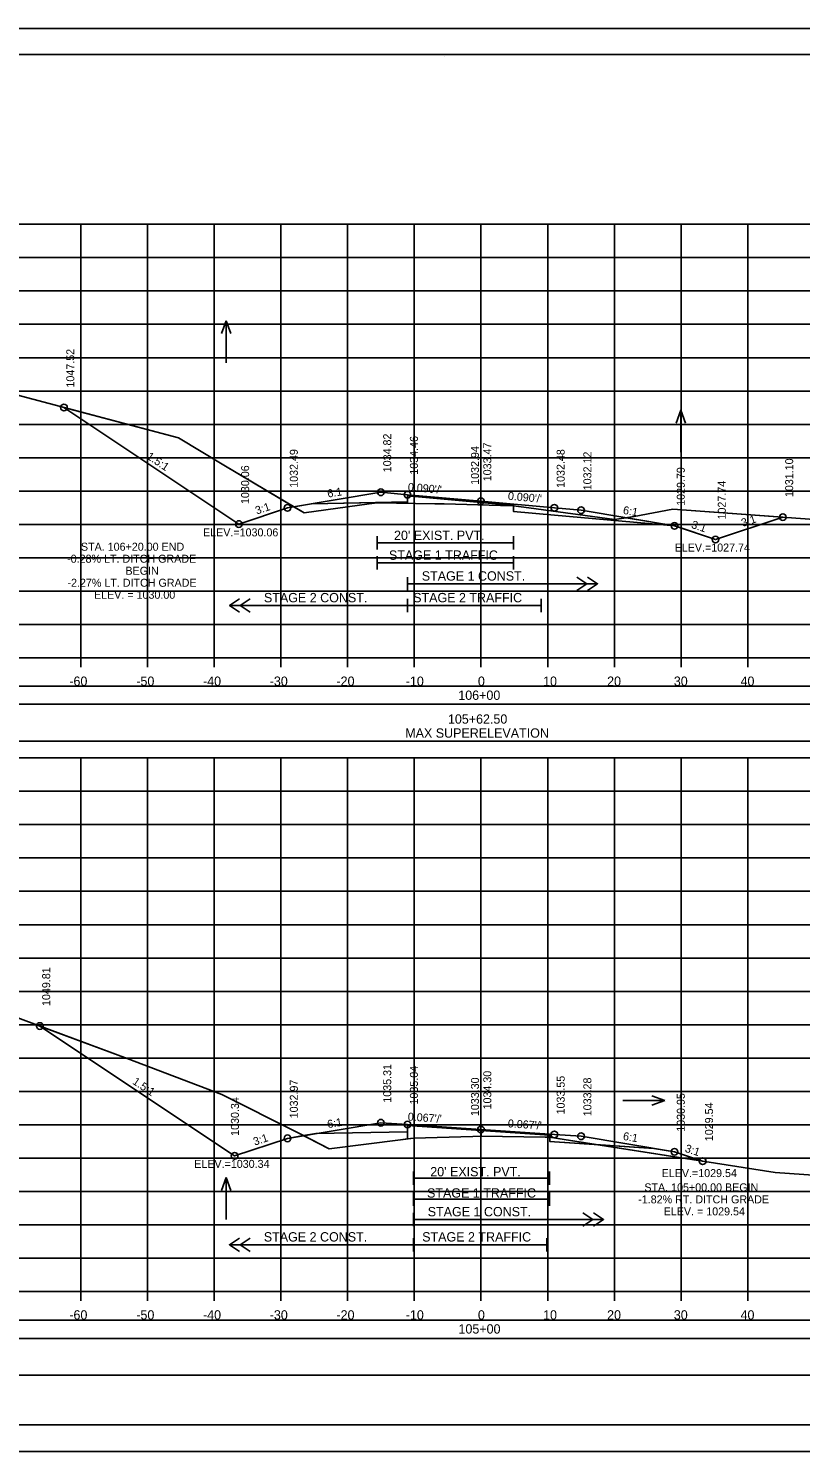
# Model space of a CAD drawing. Extents: x 1370565 to 1374448, y 301010 to 304637.
# Drawn here: x 1370667.2 to 1370782.9, y 301650.5 to 301863.8 of the extents above; entities that cross this region are included whole.
import ezdxf

# ---------------------------------------------------------------- set-up
doc = ezdxf.new("R2010")
doc.units = 0
for name, color, linetype in [('R_Alt Surface', 7, 'Continuous'), ('R_Axis', 7, 'Continuous'), ('R_Axis Annot', 7, 'Continuous'), ('R_Border', 7, 'Continuous'), ('R_Contours', 7, 'Continuous'), ('R_Drive', 7, 'Continuous'), ('R_Exist Surface', 7, 'Continuous'), ('R_Fin Surface', 7, 'Continuous'), ('R_Grid', 7, 'Continuous'), ('R_No Plot', 7, 'Continuous'), ('R_Water', 7, 'Continuous'), ('R_Water Annot', 7, 'Continuous'), ('R_Xsect Elev', 7, 'Continuous'), ('R_Xsect Slope', 7, 'Continuous')]:
    doc.layers.add(name, color=color, linetype=linetype)

msp = doc.modelspace()

# ---------------------------------------------------------------- linework, layer by layer
at = {"layer": 'R_Alt Surface'}
for points in [[(1370709.64, 301792.58), (1370724.03, 301792.87), (1370724.02, 301792.86), (1370724.03, 301793.78), (1370735.03, 301792.79), (1370739.91, 301792.35), (1370739.92, 301791.43), (1370746.03, 301790.89), (1370764.07, 301789.26)], [(1370719.47, 301787.72), (1370719.47, 301785.72)], [(1370739.91, 301787.72), (1370739.91, 301785.72)], [(1370719.47, 301786.72), (1370739.91, 301786.72)], [(1370719.47, 301784.74), (1370719.47, 301782.74)], [(1370719.47, 301783.74), (1370739.91, 301783.74)], [(1370739.91, 301784.74), (1370739.91, 301782.74)], [(1370724.03, 301781.6), (1370724.03, 301779.6)], [(1370749.42, 301781.6), (1370750.92, 301780.6), (1370749.42, 301779.6)], [(1370751.02, 301781.6), (1370752.52, 301780.6), (1370751.02, 301779.6)], [(1370724.03, 301780.6), (1370752.52, 301780.6)], [(1370698.84, 301778.34), (1370697.34, 301777.34), (1370698.84, 301776.34)], [(1370697.34, 301777.34), (1370724.03, 301777.34)], [(1370700.44, 301778.34), (1370698.94, 301777.34), (1370700.44, 301776.34)], [(1370724.03, 301778.34), (1370724.03, 301776.34)], [(1370724.03, 301777.34), (1370744.03, 301777.34)], [(1370744.04, 301778.34), (1370744.04, 301776.34)], [(1370710.26, 301698.17), (1370724.03, 301698.44), (1370724.02, 301698.44), (1370724.03, 301699.36), (1370735.03, 301698.62), (1370745.32, 301697.92), (1370745.33, 301697), (1370746.03, 301696.96), (1370760.95, 301695.95)], [(1370724.92, 301692.5), (1370724.92, 301690.5)], [(1370724.92, 301691.5), (1370745.32, 301691.5)], [(1370745.32, 301692.5), (1370745.32, 301690.5)], [(1370724.92, 301689.35), (1370724.92, 301687.35)], [(1370745.32, 301689.35), (1370745.32, 301687.35)], [(1370724.92, 301688.35), (1370745.32, 301688.35)], [(1370724.92, 301686.31), (1370724.92, 301684.31)], [(1370724.92, 301685.31), (1370753.41, 301685.31)], [(1370750.31, 301686.31), (1370751.81, 301685.31), (1370750.31, 301684.31)], [(1370751.91, 301686.31), (1370753.41, 301685.31), (1370751.91, 301684.31)], [(1370698.83, 301682.51), (1370697.33, 301681.51), (1370698.83, 301680.51)], [(1370697.33, 301681.51), (1370725.03, 301681.51)], [(1370700.43, 301682.51), (1370698.93, 301681.51), (1370700.43, 301680.51)], [(1370724.92, 301682.51), (1370724.92, 301680.51)], [(1370724.92, 301681.51), (1370744.92, 301681.51)], [(1370744.92, 301682.51), (1370744.92, 301680.51)]]:
    msp.add_lwpolyline(points, dxfattribs=at)
at = {"layer": 'R_Axis'}
for p, q in [((1370585.03, 301769.49), (1370885.03, 301769.49)), ((1370675.03, 301768.09), (1370675.03, 301769.49)), ((1370685.03, 301768.09), (1370685.03, 301769.49)), ((1370695.03, 301768.09), (1370695.03, 301769.49)), ((1370705.03, 301768.09), (1370705.03, 301769.49)), ((1370715.03, 301768.09), (1370715.03, 301769.49)), ((1370725.03, 301768.09), (1370725.03, 301769.49)), ((1370735.03, 301768.09), (1370735.03, 301769.49)), ((1370745.03, 301768.09), (1370745.03, 301769.49)), ((1370755.03, 301768.09), (1370755.03, 301769.49)), ((1370765.03, 301768.09), (1370765.03, 301769.49)), ((1370775.03, 301768.09), (1370775.03, 301769.49)), ((1370585.03, 301674.49), (1370885.03, 301674.49)), ((1370675.03, 301673.09), (1370675.03, 301674.49)), ((1370685.03, 301673.09), (1370685.03, 301674.49)), ((1370695.03, 301673.09), (1370695.03, 301674.49)), ((1370705.03, 301673.09), (1370705.03, 301674.49)), ((1370715.03, 301673.09), (1370715.03, 301674.49)), ((1370725.03, 301673.09), (1370725.03, 301674.49)), ((1370735.03, 301673.09), (1370735.03, 301674.49)), ((1370745.03, 301673.09), (1370745.03, 301674.49)), ((1370755.03, 301673.09), (1370755.03, 301674.49)), ((1370765.03, 301673.09), (1370765.03, 301674.49)), ((1370775.03, 301673.09), (1370775.03, 301674.49))]:
    msp.add_line(p, q, dxfattribs=at)
for points in [[(1370719.47, 301787.72), (1370719.47, 301785.72)], [(1370739.91, 301787.72), (1370739.91, 301785.72)], [(1370719.47, 301786.72), (1370739.91, 301786.72)], [(1370719.47, 301784.74), (1370719.47, 301782.74)], [(1370719.47, 301783.74), (1370739.91, 301783.74)], [(1370739.91, 301784.74), (1370739.91, 301782.74)], [(1370724.92, 301692.5), (1370724.92, 301690.5)], [(1370724.92, 301691.5), (1370745.32, 301691.5)], [(1370745.32, 301692.5), (1370745.32, 301690.5)], [(1370724.92, 301689.35), (1370724.92, 301687.35)], [(1370745.32, 301689.35), (1370745.32, 301687.35)], [(1370724.92, 301688.35), (1370745.32, 301688.35)]]:
    msp.add_lwpolyline(points, dxfattribs=at)
at = {"layer": 'R_Border'}
for p, q in [((1370577.03, 301859.95), (1370893.21, 301859.95)), ((1370729.55, 301859.69), (1370729.55, 301859.69)), ((1370729.55, 301859.69), (1370729.55, 301859.69)), ((1370893.21, 301654.49), (1370577.03, 301654.49))]:
    msp.add_line(p, q, dxfattribs=at)
at = {"layer": 'R_Contours'}
for p, q in [((1370706.99, 301792.14), (1370696.51, 301798.36)), ((1370709.64, 301792.58), (1370706.99, 301792.14)), ((1370719.47, 301792.78), (1370709.64, 301792.58)), ((1370724.03, 301792.87), (1370719.47, 301792.78)), ((1370724.02, 301792.66), (1370724.03, 301792.87)), ((1370724.02, 301792.86), (1370724.02, 301792.62)), ((1370756.79, 301790.48), (1370755.05, 301790.22)), ((1370756.79, 301790.48), (1370764.07, 301789.26)), ((1370764.07, 301789.26), (1370756.79, 301790.48)), ((1370708.45, 301697.87), (1370707.43, 301698.39)), ((1370710.26, 301698.17), (1370708.45, 301697.87)), ((1370724.03, 301698.44), (1370710.26, 301698.17)), ((1370724.02, 301698.44), (1370724.02, 301697.38)), ((1370724.02, 301697.38), (1370724.03, 301698.44)), ((1370724.03, 301698.44), (1370724.02, 301697.38)), ((1370735.06, 301698.62), (1370735.03, 301698.62)), ((1370735.06, 301698.62), (1370735.07, 301697.79)), ((1370735.07, 301697.79), (1370735.06, 301698.62)), ((1370745.33, 301697.64), (1370745.33, 301697)), ((1370760.95, 301695.95), (1370752.25, 301696.54)), ((1370752.25, 301696.54), (1370768.26, 301694.03))]:
    msp.add_line(p, q, dxfattribs=at)
for points in [[(1370696.51, 301798.36), (1370689.67, 301802.48), (1370672.53, 301807.01)], [(1370672.53, 301807.01), (1370698.73, 301789.55), (1370706.03, 301791.98), (1370706.99, 301792.14)], [(1370706.99, 301792.14), (1370708.53, 301791.22), (1370718.26, 301792.56), (1370719.47, 301792.72)], [(1370719.47, 301792.72), (1370719.47, 301792.78)], [(1370719.47, 301792.78), (1370719.47, 301792.72)], [(1370719.47, 301792.72), (1370724.02, 301792.66), (1370724.02, 301792.66)], [(1370755.05, 301790.22), (1370742.2, 301791.97), (1370739.91, 301792.3)], [(1370739.91, 301792.3), (1370739.92, 301791.43), (1370746.03, 301790.89), (1370764.07, 301789.26)], [(1370780.28, 301790.59), (1370763.8, 301791.8), (1370757.99, 301790.66), (1370756.79, 301790.48)], [(1370764.07, 301789.26), (1370770.18, 301787.23), (1370780.28, 301790.59)], [(1370707.43, 301698.39), (1370696.18, 301704.03), (1370681.98, 301709.45), (1370668.91, 301714.3)], [(1370668.91, 301714.3), (1370698.11, 301694.83), (1370706.03, 301697.46), (1370708.45, 301697.87)], [(1370708.45, 301697.87), (1370712.28, 301695.91), (1370722.96, 301697.24), (1370724.02, 301697.38)], [(1370724.02, 301697.38), (1370724.92, 301697.5), (1370733.82, 301697.75), (1370735.07, 301697.79)], [(1370735.03, 301698.62), (1370724.03, 301699.36), (1370724.03, 301698.44)], [(1370745.33, 301697.64), (1370745.32, 301697.92), (1370735.06, 301698.62)], [(1370735.07, 301697.79), (1370744.65, 301697.65), (1370745.32, 301697.64)], [(1370745.32, 301697.64), (1370745.33, 301697.64)], [(1370752.25, 301696.54), (1370747.49, 301697.29), (1370745.33, 301697.64)], [(1370745.33, 301697), (1370746.03, 301696.96), (1370752.25, 301696.54)], [(1370768.26, 301694.03), (1370764.03, 301695.44), (1370760.95, 301695.95)]]:
    msp.add_lwpolyline(points, dxfattribs=at)
at = {"layer": 'R_Drive'}
for points in [[(1370585.82, 301762.53), (1370884.24, 301762.53), (1370884.24, 301765.23), (1370585.82, 301765.23)], [(1370585.82, 301757.01), (1370884.24, 301757.01), (1370884.24, 301762.53), (1370585.82, 301762.53)], [(1370585.82, 301667.47), (1370884.24, 301667.47), (1370884.24, 301670.18), (1370585.82, 301670.18)], [(1370585.82, 301661.95), (1370884.24, 301661.95), (1370884.24, 301667.47), (1370585.82, 301667.47)]]:
    msp.add_lwpolyline(points, close=True, dxfattribs=at)
at = {"layer": 'R_Exist Surface'}
for points in [[(1370585.03, 301823.09), (1370587.14, 301822.88), (1370589.87, 301822.66), (1370596.68, 301822.02), (1370600.3, 301821.49), (1370655.44, 301811.49), (1370657.27, 301811.07), (1370659.72, 301810.4), (1370689.67, 301802.48), (1370696.51, 301798.36), (1370708.53, 301791.22), (1370718.26, 301792.56), (1370719.47, 301792.72), (1370728.13, 301792.6), (1370729.5, 301792.6), (1370737.94, 301792.35), (1370739.91, 301792.3), (1370742.2, 301791.97), (1370755.05, 301790.22), (1370757.99, 301790.66), (1370763.8, 301791.8), (1370791.83, 301789.74)], [(1370585.03, 301739.76), (1370654.67, 301719.57), (1370681.98, 301709.45), (1370696.18, 301704.03), (1370707.43, 301698.39), (1370712.28, 301695.91), (1370722.96, 301697.24), (1370724.92, 301697.5), (1370733.82, 301697.75), (1370735.07, 301697.79), (1370744.65, 301697.65), (1370745.32, 301697.64), (1370747.49, 301697.29), (1370779.11, 301692.32), (1370787.74, 301691.72), (1370818.07, 301689.7), (1370860.42, 301688.45), (1370868.77, 301688.21), (1370876.05, 301688.04), (1370885.03, 301687.88)]]:
    msp.add_lwpolyline(points, dxfattribs=at)
at = {"layer": 'R_Fin Surface'}
for points in [[(1370672.53, 301807.01), (1370698.73, 301789.55), (1370706.03, 301791.98), (1370720.03, 301794.31), (1370724.03, 301793.95), (1370735.03, 301792.96), (1370746.03, 301791.97), (1370750.03, 301791.61), (1370764.03, 301789.28), (1370770.18, 301787.23), (1370780.28, 301790.59)], [(1370668.91, 301714.3), (1370698.11, 301694.83), (1370706.03, 301697.46), (1370720.03, 301699.8), (1370724.03, 301699.53), (1370735.03, 301698.79), (1370746.03, 301698.04), (1370750.03, 301697.77), (1370764.03, 301695.44), (1370768.26, 301694.03)]]:
    msp.add_lwpolyline(points, dxfattribs=at)
at = {"layer": 'R_Grid'}
for p, q in [((1370585.03, 301834.49), (1370885.03, 301834.49)), ((1370675.03, 301769.49), (1370675.03, 301834.49)), ((1370685.03, 301769.49), (1370685.03, 301834.49)), ((1370695.03, 301769.49), (1370695.03, 301834.49)), ((1370705.03, 301769.49), (1370705.03, 301834.49)), ((1370715.03, 301769.49), (1370715.03, 301834.49)), ((1370725.03, 301769.49), (1370725.03, 301834.49)), ((1370735.03, 301769.49), (1370735.03, 301834.49)), ((1370745.03, 301769.49), (1370745.03, 301834.49)), ((1370755.03, 301769.49), (1370755.03, 301834.49)), ((1370765.03, 301769.49), (1370765.03, 301834.49)), ((1370775.03, 301769.49), (1370775.03, 301834.49)), ((1370585.03, 301829.49), (1370885.03, 301829.49)), ((1370585.03, 301824.49), (1370885.03, 301824.49)), ((1370585.03, 301819.49), (1370885.03, 301819.49)), ((1370585.03, 301814.49), (1370885.03, 301814.49)), ((1370585.03, 301809.49), (1370885.03, 301809.49)), ((1370585.03, 301804.49), (1370885.03, 301804.49)), ((1370585.03, 301799.49), (1370885.03, 301799.49)), ((1370585.03, 301794.49), (1370885.03, 301794.49)), ((1370585.03, 301789.49), (1370885.03, 301789.49)), ((1370585.03, 301784.49), (1370885.03, 301784.49)), ((1370585.03, 301779.49), (1370885.03, 301779.49)), ((1370585.03, 301774.49), (1370885.03, 301774.49)), ((1370585.03, 301769.49), (1370885.03, 301769.49)), ((1370585.03, 301754.49), (1370885.03, 301754.49)), ((1370675.03, 301674.49), (1370675.03, 301754.49)), ((1370685.03, 301674.49), (1370685.03, 301754.49)), ((1370695.03, 301674.49), (1370695.03, 301754.49)), ((1370705.03, 301674.49), (1370705.03, 301754.49)), ((1370715.03, 301674.49), (1370715.03, 301754.49)), ((1370725.03, 301674.49), (1370725.03, 301754.49)), ((1370735.03, 301674.49), (1370735.03, 301754.49)), ((1370745.03, 301674.49), (1370745.03, 301754.49)), ((1370755.03, 301674.49), (1370755.03, 301754.49)), ((1370765.03, 301674.49), (1370765.03, 301754.49)), ((1370775.03, 301674.49), (1370775.03, 301754.49)), ((1370585.03, 301749.49), (1370885.03, 301749.49)), ((1370585.03, 301744.49), (1370885.03, 301744.49)), ((1370585.03, 301739.49), (1370885.03, 301739.49)), ((1370585.03, 301734.49), (1370885.03, 301734.49)), ((1370585.03, 301729.49), (1370885.03, 301729.49)), ((1370585.03, 301724.49), (1370885.03, 301724.49)), ((1370585.03, 301719.49), (1370885.03, 301719.49)), ((1370585.03, 301714.49), (1370885.03, 301714.49)), ((1370585.03, 301709.49), (1370885.03, 301709.49)), ((1370585.03, 301704.49), (1370885.03, 301704.49)), ((1370585.03, 301699.49), (1370885.03, 301699.49)), ((1370585.03, 301694.49), (1370885.03, 301694.49)), ((1370585.03, 301689.49), (1370885.03, 301689.49)), ((1370585.03, 301684.49), (1370885.03, 301684.49)), ((1370585.03, 301679.49), (1370885.03, 301679.49)), ((1370585.03, 301674.49), (1370885.03, 301674.49))]:
    msp.add_line(p, q, dxfattribs=at)
at = {"layer": 'R_No Plot'}
for p, q in [((1370564.63, 301863.84), (1370897.96, 301863.84)), ((1370564.63, 301650.51), (1370897.96, 301650.51))]:
    msp.add_line(p, q, dxfattribs=at)
for points in [[(1370564.62, 301863.84), (1370897.96, 301863.84), (1370897.96, 301650.51), (1370564.62, 301650.51)], [(1370810.95, 301859.95), (1370830.57, 301859.95), (1370830.57, 301850.07), (1370846.68, 301850.07), (1370869.88, 301850.07), (1370869.88, 301817.4), (1370893.09, 301817.4), (1370893.21, 301654.49), (1370577.03, 301654.49), (1370577.03, 301859.95)]]:
    msp.add_lwpolyline(points, close=True, dxfattribs=at)
for centre in [(1370672.53, 301807.01), (1370720.03, 301794.31), (1370724.03, 301793.95), (1370706.03, 301791.98), (1370735.03, 301792.96), (1370746.03, 301791.97), (1370750.03, 301791.61), (1370698.73, 301789.55), (1370764.03, 301789.28), (1370780.28, 301790.59), (1370770.18, 301787.23), (1370668.91, 301714.3), (1370720.03, 301699.8), (1370724.03, 301699.53), (1370706.03, 301697.46), (1370735.03, 301698.79), (1370746.03, 301698.04), (1370750.03, 301697.77), (1370764.03, 301695.44), (1370698.11, 301694.83), (1370768.26, 301694.03)]:
    msp.add_circle(centre, 0.5, dxfattribs=at)
at = {"layer": 'R_Water Annot'}
for p, q in [((1370696.85, 301820.02), (1370696.15, 301818.1)), ((1370696.85, 301813.74), (1370696.85, 301820.02)), ((1370696.85, 301820.02), (1370697.55, 301818.1)), ((1370765.01, 301806.6), (1370764.31, 301804.67)), ((1370765.01, 301800.31), (1370765.01, 301806.6)), ((1370765.01, 301806.6), (1370765.71, 301804.67)), ((1370756.29, 301703.11), (1370762.57, 301703.11)), ((1370762.57, 301703.11), (1370760.65, 301703.81)), ((1370762.57, 301703.11), (1370760.65, 301702.41)), ((1370696.85, 301691.59), (1370696.15, 301689.66)), ((1370696.85, 301685.3), (1370696.85, 301691.59)), ((1370696.85, 301691.59), (1370697.55, 301689.66))]:
    msp.add_line(p, q, dxfattribs=at)
at = {"layer": 'R_Xsect Elev'}
for p, q in [((1370735.03, 301792.43), (1370735.03, 301802.43)), ((1370735.03, 301697.79), (1370735.03, 301707.79))]:
    msp.add_line(p, q, dxfattribs=at)

# ---------------------------------------------------------------- texts
at = {"layer": 'R_Axis Annot'}
for s, p in [("20' EXIST. PVT.", (1370722, 301787.16)), ('-60', (1370673.33, 301765.29)), ('-50', (1370683.37, 301765.29)), ('-40', (1370693.37, 301765.29)), ('-30', (1370703.37, 301765.29)), ('-20', (1370713.37, 301765.29)), ('-10', (1370723.76, 301765.29)), ('0', (1370734.57, 301765.29)), ('10', (1370744.34, 301765.29)), ('20', (1370753.94, 301765.29)), ('30', (1370763.94, 301765.29)), ('40', (1370773.94, 301765.29)), ('106+00', (1370731.63, 301763.19)), ('105+62.50', (1370730.08, 301759.62)), ('MAX SUPERELEVATION', (1370723.68, 301757.52)), ("20' EXIST. PVT.", (1370727.43, 301691.76)), ('-60', (1370673.33, 301670.29)), ('-50', (1370683.37, 301670.29)), ('-40', (1370693.37, 301670.29)), ('-30', (1370703.37, 301670.29)), ('-20', (1370713.37, 301670.29)), ('-10', (1370723.76, 301670.29)), ('0', (1370734.57, 301670.29)), ('10', (1370744.34, 301670.29)), ('20', (1370753.94, 301670.29)), ('30', (1370763.94, 301670.29)), ('40', (1370773.94, 301670.29)), ('105+00', (1370731.66, 301668.19))]:
    msp.add_text(s, height=1.4, dxfattribs=at).set_placement(p)
at = {"layer": 'R_Water'}
for s, p in [('STAGE 1 TRAFFIC', (1370721.24, 301784.19)), ('STAGE 1 CONST.', (1370726.16, 301781.07)), ('STAGE 2 CONST.', (1370702.5, 301777.82)), ('STAGE 2 TRAFFIC', (1370724.87, 301777.82)), ('STAGE 1 TRAFFIC', (1370726.95, 301688.57)), ('STAGE 1 CONST.', (1370727.05, 301685.77)), ('STAGE 2 CONST.', (1370702.48, 301681.99)), ('STAGE 2 TRAFFIC', (1370726.22, 301681.99))]:
    msp.add_text(s, height=1.4, dxfattribs=at).set_placement(p)
at = {"layer": 'R_Xsect Elev'}
for s, p in [('1047.52', (1370674.08, 301810.01)), ('1034.82', (1370721.58, 301797.31)), ('1034.46', (1370725.58, 301796.95)), ('1032.49', (1370707.58, 301794.98)), ('1032.94', (1370734.73, 301795.43)), ('1033.47', (1370736.58, 301795.96)), ('1032.48', (1370747.58, 301794.97)), ('1032.12', (1370751.58, 301794.61)), ('1030.06', (1370700.28, 301792.55)), ('1031.10', (1370781.83, 301793.59)), ('1029.79', (1370765.58, 301792.28)), ('1027.74', (1370771.73, 301790.23)), ('1049.81', (1370670.46, 301717.3)), ('1035.31', (1370721.58, 301702.8)), ('1035.04', (1370725.58, 301702.53)), ('1033.30', (1370734.73, 301700.79)), ('1034.30', (1370736.58, 301701.79)), ('1033.55', (1370747.58, 301701.04)), ('1033.28', (1370751.58, 301700.77)), ('1032.97', (1370707.58, 301700.46)), ('1030.95', (1370765.58, 301698.44)), ('1030.34', (1370698.75, 301697.83)), ('1029.54', (1370769.81, 301697.03))]:
    msp.add_text(s, height=1.2, rotation=90, dxfattribs=at).set_placement(p)
for s, p in [('ELEV.=1030.06', (1370693.37, 301787.7)), ('STA. 106+20.00 END', (1370675.07, 301785.55)), ('ELEV.=1027.74', (1370764.06, 301785.43)), ('-0.28% LT. DITCH GRADE', (1370673, 301783.75)), ('BEGIN', (1370681.74, 301781.95)), ('-2.27% LT. DITCH GRADE', (1370673.05, 301780.15)), ('ELEV. = 1030.00', (1370677.03, 301778.35)), ('ELEV.=1030.34', (1370692.05, 301693.03)), ('ELEV.=1029.54', (1370762.11, 301691.65)), ('STA. 105+00.00 BEGIN ', (1370759.52, 301689.51)), ('-1.82% RT. DITCH GRADE', (1370758.6, 301687.71)), ('ELEV. = 1029.54', (1370762.42, 301685.91))]:
    msp.add_text(s, height=1.2, dxfattribs=at).set_placement(p)
at = {"layer": 'R_Xsect Slope'}
for s, rotation, p in [('1.5:1', 326.3086, (1370684.81, 301799.43)), ('6:1', 9.4642, (1370712.1, 301793.5)), ("0.090'/'", 354.8572, (1370724.03, 301794.55)), ("0.090'/'", 354.8572, (1370739.03, 301793.2)), ('3:1', 18.4349, (1370701.43, 301790.97)), ('6:1', 350.5358, (1370756.26, 301791.08)), ('3:1', 341.5651, (1370766.47, 301788.99)), ('3:1', 18.4332, (1370774.28, 301789.12)), ('1.5:1', 326.3086, (1370682.69, 301705.71)), ('6:1', 9.4642, (1370712.1, 301698.98)), ("0.067'/'", 356.1384, (1370724.03, 301700.13)), ("0.067'/'", 356.1384, (1370739.03, 301699.12)), ('3:1', 18.4349, (1370701.12, 301696.36)), ('6:1', 350.5358, (1370756.26, 301697.24)), ('3:1', 341.5651, (1370765.51, 301695.47))]:
    msp.add_text(s, height=1.2, rotation=rotation, dxfattribs=at).set_placement(p)

doc.saveas('drawing.dxf')
